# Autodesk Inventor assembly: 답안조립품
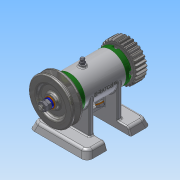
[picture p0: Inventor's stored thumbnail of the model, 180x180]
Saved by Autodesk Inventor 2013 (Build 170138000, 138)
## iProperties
Created: 2016-07
Part Number: 답안조립품
Document SubType Name: Assembly
Designer: Administrator
Author: Administrator
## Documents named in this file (16)
- C:\Users\Administrator\Desktop\460708V1002\답안조립품.iam
- C:\Users\Administrator\Desktop\460708V1002\본체.ipt
- C:\Users\Administrator\Desktop\460708V1002\베어링 15 x 32 x 9.ipt
- C:\Users\Administrator\Desktop\460708V1002\축.ipt
- C:\Users\Administrator\Desktop\460708V1002\키 3 x 3 x 12.ipt
- C:\Users\Administrator\Desktop\460708V1002\V벨트풀리.ipt
- C:\Users\Administrator\Desktop\460708V1002\스퍼기어.ipt
- C:\Users\Administrator\Desktop\460708V1002\와셔 8x17.ipt
- C:\Users\Administrator\Desktop\460708V1002\스프링와셔 8.ipt
- C:\Users\Administrator\Desktop\460708V1002\너트 M 8.ipt
- C:\Users\Administrator\Desktop\460708V1002\커버.ipt
- C:\Users\Administrator\Desktop\460708V1002\오일 실 15 25 7.ipt
- C:\Users\Administrator\Desktop\460708V1002\볼트 M4 x 12.ipt
- C:\Users\Administrator\Desktop\460708V1002\볼트 M 6 x 8.ipt
- C:\Users\Administrator\Desktop\460708V1002\와셔 6x11.5.ipt
- C:\Users\Administrator\Desktop\460708V1002\니플 M 6 x 0.75.ipt
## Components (11 placed, 3 different names)
1. KS B 2023 6002 - 15 x 32 x 9:1
2. KS B 2023 6002 - 15 x 32 x 9:2
3. V벨트풀리:1
4. ISO 4762 M4 x 12:2
5. ISO 4762 M4 x 12:1
6. ISO 4762 M4 x 12:3
7. ISO 4762 M4 x 12:4
8. ISO 4762 M4 x 12:5
9. ISO 4762 M4 x 12:6
10. ISO 4762 M4 x 12:7
11. ISO 4762 M4 x 12:8
